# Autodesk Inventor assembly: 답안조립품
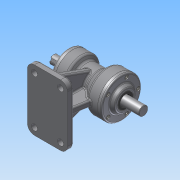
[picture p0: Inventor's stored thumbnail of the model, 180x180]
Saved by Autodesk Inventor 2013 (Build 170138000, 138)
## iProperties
Created: 2015-08
Part Number: 답안조립품
Document SubType Name: Assembly
Designer: Administrator
Author: Administrator
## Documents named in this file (10)
- C:\Users\Administrator\Desktop\450806V1018\답안조립품.iam
- C:\Users\Administrator\Desktop\450806V1018\본체.ipt
- C:\Users\Administrator\Desktop\450806V1018\M4x0.5.ipt
- C:\Users\Administrator\Desktop\450806V1018\뒤커버.ipt
- C:\Users\Administrator\Desktop\450806V1018\베어링 6203.ipt
- C:\Users\Administrator\Desktop\450806V1018\베어링 6205.ipt
- C:\Users\Administrator\Desktop\450806V1018\앞커버.ipt
- C:\Users\Administrator\Desktop\450806V1018\오일실 .ipt
- 오일실 .ipt
- C:\Users\Administrator\Desktop\450806V1018\축.ipt
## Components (10 placed, 1 different names)
1. M4x0.5:1
2. M4x0.5:2
3. M4x0.5:3
4. M4x0.5:4
5. M4x0.5:5
6. M4x0.5:6
7. M4x0.5:7
8. M4x0.5:8
9. M4x0.5:9
10. M4x0.5:10
